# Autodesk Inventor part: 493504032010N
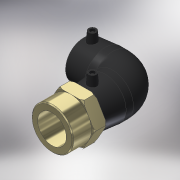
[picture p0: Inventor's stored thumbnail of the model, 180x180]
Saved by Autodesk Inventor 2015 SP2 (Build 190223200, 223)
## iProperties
Created: 2017-06
Part Number: 493504032010N
Material: Generic
Description: PLASSON 90° ELBOW FEMALE TRANSITION 32 x 1''
Document SubType Name: Modeling
Designer: KIM
Mass: 132.451 g
Surface Area: 429.305 cm^2
Volume: 132.451 cm^3
Density: 1 g/cm^3
Appearance: Rubber - Black
Author: KIM
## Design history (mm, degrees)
derived "493504.ipt"
feature "Solid1::493504.ipt"
tag "TaggingFeature1"
body "Solid1"
other parameters: "d2" = 44, "d4" = 27.66667, "d5" = 39.6, "d8" = 168 deg, "d10" = 17.6, "d11" = 5.86667, "d29" = 42, "d30" = 15, "d31" = 45.65, "d34" = 5 deg, "d41" = 4, "d42" = 14, "d43" = 0, "d48" = 61, "d49" = 32, "d50" = 27.2, "d51" = 17.6, "d52" = 44, "d54" = 90 deg, "d57" = 32, "d58" = 44, "d59" = 0, "d61" = 90 deg, "d86" = 3, "d87" = 0, "d93" = 0.1, "d96" = 30.291, "d97" = 27, "d99" = 44, "d100" = 32, "d107" = 16, "d108" = 0, "d109" = 0.96, "d112" = 45 deg, "d113" = 45 deg, "d114" = 1.6, "d_" = 32, "L_" = 123, "L_1" = 44, "D_" = 27, "A_" = 42, "d_2" = 12, "D_1" = 44, "Rp_" = 30.291
